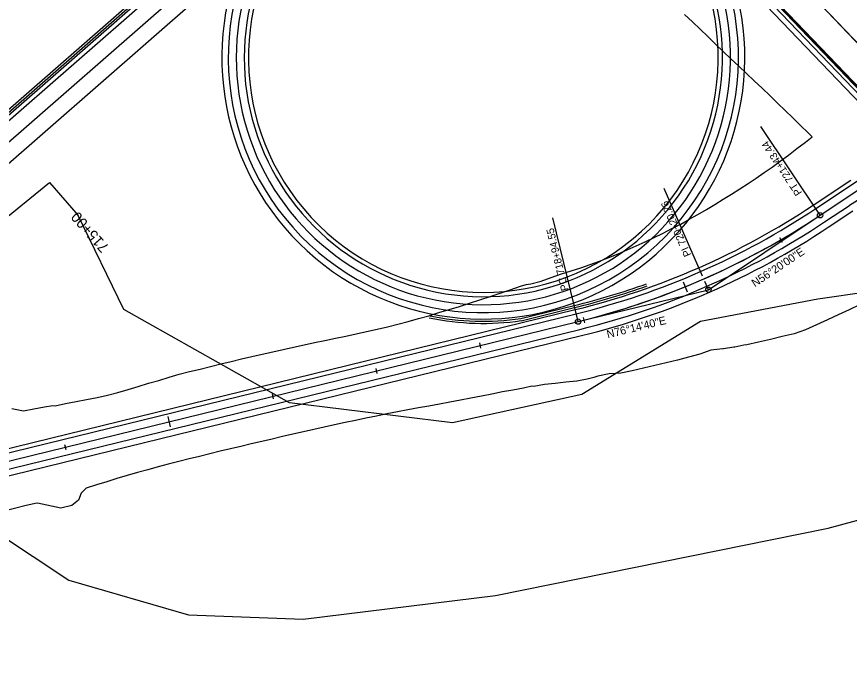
# Model space of a CAD drawing. Extents: x 1300404 to 1323571, y 237813 to 252077.
# Drawn here: x 1310373 to 1311153, y 240028 to 240634 of the extents above; entities that cross this region are included whole.
import ezdxf

# ---------------------------------------------------------------- set-up
doc = ezdxf.new("R2010")
doc.units = 0
for name, color, linetype in [('R_Const Limits', 7, 'Continuous'), ('R_Curb', 7, 'Continuous'), ('R_Flooplain', 7, 'Continuous'), ('R_Future', 7, 'Continuous'), ('R_Horz Alg Annot', 7, 'Continuous'), ('R_Horz Alg Annot Leader', 7, 'Continuous'), ('R_Horz Alg Major Ticks', 7, 'Continuous'), ('R_Horz Alg Minor Ticks', 7, 'Continuous'), ('R_Horz Alg Station Annot', 7, 'Continuous'), ('R_Horz Alg Tangents', 7, 'Continuous'), ('R_Horz Alg Tangents Text', 7, 'Continuous'), ('R_Lane Edge', 7, 'Continuous'), ('R_Proposed', 7, 'Continuous'), ('R_Shoulder', 7, 'Continuous'), ('R_Sidewalk Edge', 7, 'Continuous')]:
    doc.layers.add(name, color=color, linetype=linetype)

msp = doc.modelspace()

# ---------------------------------------------------------------- linework, layer by layer
at = {"layer": 'R_Const Limits'}
for points in [[(1311118.05, 240520.86), (1311114.24, 240524.63), (1311107.14, 240531.68), (1311100.03, 240538.72), (1311092.93, 240545.76), (1311085.66, 240552.65), (1311078.41, 240559.55), (1311071.16, 240566.46), (1311063.88, 240573.33), (1311056.6, 240580.21), (1311049.31, 240587.08), (1311042.09, 240594.01), (1311034.89, 240600.96), (1311027.69, 240607.92), (1311020.45, 240614.83), (1311013.19, 240621.72), (1311005.93, 240628.61), (1310998.7, 240635.54)], [(1310368.48, 240266.27), (1310379.32, 240264.05), (1310389.15, 240265.97), (1310398.98, 240267.86), (1310406.93, 240269.33), (1310408.99, 240269.02), (1310418.82, 240270.93), (1310428.64, 240272.86), (1310438.46, 240274.81), (1310448.28, 240276.77), (1310458.09, 240278.74), (1310467.77, 240281.25), (1310477.34, 240284.21), (1310486.92, 240287.14), (1310496.5, 240290.06), (1310506.16, 240292.63), (1310515.71, 240295.67), (1310525.3, 240298.57), (1310535.01, 240300.97), (1310544.71, 240303.39), (1310554.42, 240305.78), (1310564.14, 240308.13), (1310573.86, 240310.49), (1310583.59, 240312.8), (1310593.33, 240315.06), (1310603.08, 240317.29), (1310612.83, 240319.52), (1310622.6, 240321.67), (1310632.35, 240323.88), (1310642.13, 240325.99), (1310651.9, 240328.13), (1310661.69, 240330.21), (1310671.48, 240332.27), (1310681.28, 240334.28), (1310691.05, 240336.45), (1310700.82, 240338.6), (1310710.59, 240340.73), (1310720.38, 240342.79), (1310730.05, 240345.34), (1310739.7, 240347.99), (1310749.35, 240350.62), (1310758.99, 240353.3), (1310768.57, 240356.23), (1310778.14, 240359.16), (1310787.72, 240362.11), (1310797.29, 240365.07), (1310806.82, 240368.2), (1310816.36, 240371.28), (1310825.91, 240374.33), (1310833.47, 240377.03), (1310835.39, 240377.66), (1310844.84, 240381.09), (1310850.28, 240382.58), (1310854.61, 240383.25), (1310864.32, 240385.64), (1310873.73, 240389.27), (1310883.23, 240392.49), (1310892.46, 240395.34), (1310901.33, 240398.3), (1310910.16, 240401.35), (1310918.93, 240404.52), (1310927.66, 240407.82), (1310936.29, 240411.33), (1310944.88, 240414.94), (1310953.39, 240418.69), (1310961.82, 240422.61), (1310970.21, 240426.58), (1310978.51, 240430.73), (1310986.77, 240434.92), (1310987.08, 240435.08), (1310994.15, 240438.76), (1310994.96, 240439.21), (1311001.12, 240442.66), (1311003.05, 240443.71), (1311011.12, 240448.19), (1311019.11, 240452.78), (1311026.96, 240457.62), (1311034.79, 240462.45), (1311042.65, 240467.2), (1311050.4, 240472.11), (1311058.07, 240477.13), (1311065.7, 240482.19), (1311073.21, 240487.44), (1311080.72, 240492.65), (1311088.03, 240498.14), (1311095.91, 240503.8), (1311103.87, 240509.89), (1311111.84, 240515.97), (1311118.05, 240520.86)], [(1311163, 240363.94), (1311152.83, 240358.97), (1311142.64, 240354.1), (1311132.41, 240349.35), (1311122.14, 240344.74), (1311111.86, 240340.2), (1311101.27, 240336.31), (1311090.07, 240333.71), (1311079, 240331.03), (1311067.94, 240328.47), (1311056.84, 240326.16), (1311054.22, 240325.6), (1311045.79, 240323.94), (1311044.68, 240323.73), (1311034.97, 240322.38), (1311034.54, 240322.32), (1311023.31, 240320.92), (1311012.98, 240317.41), (1311002.44, 240314.5), (1310991.85, 240311.81), (1310981.25, 240309.25), (1310970.63, 240306.83), (1310960.1, 240304.23), (1310949.57, 240301.71), (1310938.97, 240299.48), (1310927.91, 240299.02), (1310917.42, 240296.65), (1310913.68, 240295.53), (1310907.38, 240293.85), (1310897.54, 240291.99), (1310887.51, 240290.92), (1310877.46, 240289.92), (1310867.44, 240288.78), (1310857.54, 240287.15), (1310855.47, 240287.17), (1310847.65, 240285.5), (1310837.83, 240283.59), (1310827.94, 240281.92), (1310818.13, 240279.95), (1310808.3, 240278.02), (1310798.48, 240276.08), (1310788.68, 240274.07), (1310778.83, 240272.23), (1310768.94, 240270.58), (1310759.11, 240268.68), (1310749.24, 240266.97), (1310739.42, 240265.03), (1310729.57, 240263.21), (1310719.74, 240261.28), (1310709.93, 240259.31), (1310700.1, 240257.4), (1310690.32, 240255.3), (1310680.56, 240253.13), (1310670.78, 240251.01), (1310661.02, 240248.81), (1310651.26, 240246.64), (1310641.5, 240244.44), (1310631.75, 240242.23), (1310622, 240240.02), (1310612.26, 240237.74), (1310602.51, 240235.49), (1310592.78, 240233.21), (1310583.04, 240230.91), (1310573.31, 240228.6), (1310563.59, 240226.27), (1310553.87, 240223.92), (1310544.15, 240221.56), (1310534.44, 240219.17), (1310524.73, 240216.77), (1310515.03, 240214.35), (1310505.37, 240211.74), (1310495.73, 240209.07), (1310486.08, 240206.44), (1310476.45, 240203.74), (1310466.88, 240200.78), (1310457.31, 240197.81), (1310447.75, 240194.82), (1310438.18, 240191.84), (1310433.53, 240187.15), (1310433.34, 240187.09), (1310430.99, 240180.39), (1310424.76, 240175.65), (1310414.39, 240172.97), (1310392.58, 240177.58)], [(1310392.58, 240177.58), (1310390.21, 240177.5), (1310380.5, 240175.13), (1310370.79, 240172.72), (1310361.13, 240170.14), (1310355.33, 240168.6), (1310354.08, 240168.28)]]:
    msp.add_lwpolyline(points, dxfattribs=at)
at = {"layer": 'R_Curb'}
for p, q in [((1311008.13, 240726.61), (1311199.03, 240526.61)), ((1311009.39, 240724.57), (1311198.47, 240526.48))]:
    msp.add_line(p, q, dxfattribs=at)
at = {"layer": 'R_Flooplain'}
for p, q in [((1310180.38, 240295.99), (1310403.59, 240478.31)), ((1310403.59, 240478.31), (1310430.47, 240447.32)), ((1310473.27, 240359.27), (1310430.47, 240447.32)), ((1311274.47, 240390.28), (1311123.39, 240368.86)), ((1311123.39, 240368.86), (1311013.46, 240347.78)), ((1310628.59, 240271.59), (1310473.27, 240359.27)), ((1311013.46, 240347.78), (1310902.4, 240279.58)), ((1310902.4, 240279.58), (1310781.31, 240253.01)), ((1310781.31, 240253.01), (1310628.59, 240271.59)), ((1311133.26, 240154.22), (1311385.94, 240223.76)), ((1310341.11, 240159.05), (1310421.91, 240105.38)), ((1310821.64, 240091.29), (1311133.26, 240154.22)), ((1310421.91, 240105.38), (1310534.02, 240073.11)), ((1310641.48, 240068.91), (1310821.64, 240091.29)), ((1310534.02, 240073.11), (1310641.48, 240068.91))]:
    msp.add_line(p, q, dxfattribs=at)
at = {"layer": 'R_Future'}
for p, q in [((1311714.76, 241726.24), (1309950.43, 240183.5)), ((1311716.07, 241724.73), (1309951.75, 240181.99)), ((1311717.39, 241723.23), (1309953.06, 240180.49)), ((1311720.02, 241720.22), (1309955.69, 240177.48)), ((1310616.69, 240735.53), (1309965.57, 240166.18)), ((1310582.45, 240685.67), (1309975.44, 240154.89)), ((1310845.18, 240350.66), (1310895.17, 240362.89)), ((1310845.56, 240348.69), (1310895.64, 240360.95))]:
    msp.add_line(p, q, dxfattribs=at)
for centre, radius, start, end in [((1310810.12, 240595.16), 231.5, 131.16667, 43.66667), ((1310810.12, 240595.16), 231.5, 131.16667, 43.66667), ((1310810.12, 240595.16), 224, 131.16667, 43.66667), ((1310810.12, 240595.16), 220, 138.89832, 30.82805), ((1310810.12, 240595.16), 239, 144.03223, 33.16936), ((1310810.12, 240595.16), 245, 158.31916, 20.65241), ((1310728.55, 241043.5), 700.7, 283.75562, 289.5516), ((1310728.55, 241043.5), 702.7, 283.75562, 289.5516), ((1310810.12, 240595.16), 249, 258.26431, 278.18307), ((1310810.12, 240595.16), 247, 258.26431, 278.16053)]:
    msp.add_arc(centre, radius, start, end, dxfattribs=at)
at = {"layer": 'R_Horz Alg Annot Leader'}
for points in [[(1311125.58, 240447.42), (1311070.15, 240530.65)], [(1311015.46, 240390.25), (1310979.37, 240472.41)], [(1310898.85, 240347.84), (1310875.07, 240444.97)], [(1311020.96, 240377.73), (1311017.54, 240385.52)]]:
    msp.add_lwpolyline(points, dxfattribs=at)
at = {"layer": 'R_Horz Alg Major Ticks'}
for points in [[(1310997.17, 240384.98), (1311000.95, 240375.72)], [(1310514.43, 240258.88), (1310516.8, 240249.17)]]:
    msp.add_lwpolyline(points, dxfattribs=at)
at = {"layer": 'R_Horz Alg Minor Ticks'}
for points in [[(1311087.46, 240426.61), (1311089.98, 240422.29)], [(1310903.52, 240351.58), (1310904.75, 240346.73)], [(1310806.42, 240327.78), (1310807.6, 240322.93)], [(1310709.28, 240304.01), (1310710.47, 240299.15)], [(1310612.15, 240280.23), (1310613.34, 240275.37)], [(1310417.89, 240232.67), (1310419.08, 240227.82)]]:
    msp.add_lwpolyline(points, dxfattribs=at)
at = {"layer": 'R_Horz Alg Tangents'}
for p, q in [((1311020.96, 240377.73), (1311125.58, 240447.42)), ((1310898.85, 240347.84), (1311020.96, 240377.73))]:
    msp.add_line(p, q, dxfattribs=at)
at = {"layer": 'R_Lane Edge'}
for p, q in [((1310418.29, 241346.01), (1311200.16, 240526.88)), ((1311121.43, 240453.66), (1311169.87, 240485.93)), ((1311129.74, 240441.18), (1311152.96, 240456.64)), ((1310159.85, 240174.65), (1310897.07, 240355.12)), ((1310163.42, 240160.08), (1310900.63, 240340.55))]:
    msp.add_line(p, q, dxfattribs=at)
for centre, radius, start, end in [((1311208.4, 240373.42), 100, 43.66667, 123.66667), ((1310728.55, 241043.5), 708.7, 283.75562, 303.66667), ((1310728.55, 241043.5), 723.7, 283.75562, 303.66667)]:
    msp.add_arc(centre, radius, start, end, dxfattribs=at)
at = {"layer": 'R_Proposed'}
for p, q in [((1310151.78, 241665.77), (1311952.58, 239779.15)), ((1310165.59, 241651.3), (1311952.63, 239779.09)), ((1310165.59, 241651.3), (1311952.63, 239779.09)), ((1311125.58, 240447.42), (1311241.2, 240524.43)), ((1311125.58, 240447.42), (1311241.2, 240524.43)), ((1311125.58, 240447.42), (1311241.2, 240524.43)), ((1310161.63, 240167.37), (1310898.85, 240347.84)), ((1310161.63, 240167.37), (1310898.85, 240347.84))]:
    msp.add_line(p, q, dxfattribs=at)
for centre in [(1311125.58, 240447.42), (1311020.96, 240377.73), (1310898.85, 240347.84)]:
    msp.add_circle(centre, 2.5, dxfattribs=at)
for start in [283.75562, 284.21185, 284.21185]:
    msp.add_arc((1310728.55, 241043.5), 716.2, start, 303.66667, dxfattribs=at)
at = {"layer": 'R_Shoulder'}
for p, q in [((1311119.21, 240456.99), (1311154.26, 240480.34)), ((1311133.07, 240436.19), (1311156.29, 240451.65)), ((1310158.9, 240178.54), (1310896.12, 240359.01)), ((1310164.84, 240154.25), (1310902.06, 240334.73))]:
    msp.add_line(p, q, dxfattribs=at)
for radius in [704.7, 729.7]:
    msp.add_arc((1310728.55, 241043.5), radius, 283.75562, 303.66667, dxfattribs=at)
at = {"layer": 'R_Sidewalk Edge'}
for p, q in [((1310871.88, 240857.04), (1311196.44, 240517.02)), ((1310878.95, 240856.88), (1311198.54, 240522.06))]:
    msp.add_line(p, q, dxfattribs=at)

# ---------------------------------------------------------------- texts
at = {"layer": 'R_Horz Alg Annot'}
for s, rotation, p in [('PT 721+43.44', 123.66667, (1311108.92, 240468.68)), ('PI 720+20.26', 113.71114, (1311005.04, 240410.43)), ('PC 718+94.55', 103.75562, (1310890.03, 240377.58))]:
    msp.add_text(s, height=7, rotation=rotation, dxfattribs=at).set_placement(p)
at = {"layer": 'R_Horz Alg Station Annot'}
msp.add_text('715+00', height=10, rotation=131.16667, dxfattribs=at).set_placement((1310460.18, 240417.89))
at = {"layer": 'R_Horz Alg Tangents Text'}
for s, rotation, p in [('N56%%d20\'00"E', 33.66667, (1311064.43, 240379.92)), ('N76%%d14\'40"E', 13.75562, (1310926.67, 240332.17))]:
    msp.add_text(s, height=7.5, rotation=rotation, dxfattribs=at).set_placement(p)

doc.saveas('drawing.dxf')
